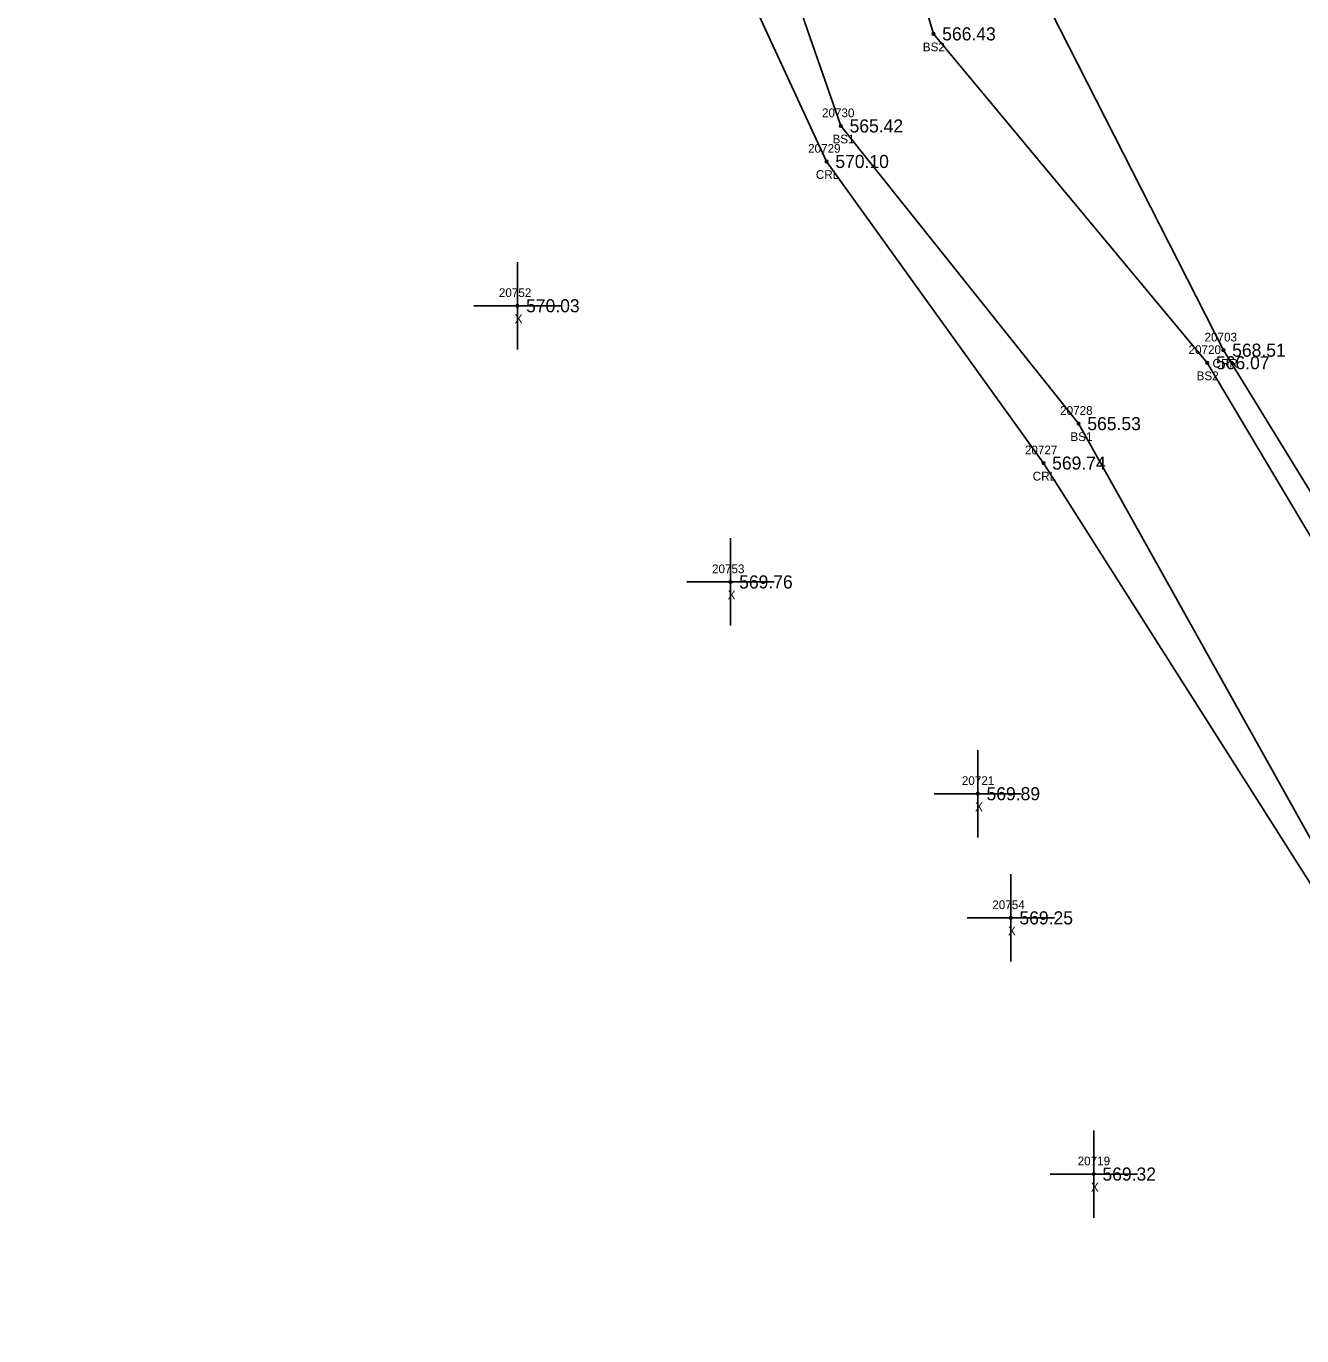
# Model space of a CAD drawing. Extents: x 1530159 to 1531652, y 877045 to 877724.
# Drawn here: x 1530609.3 to 1530755.4, y 877423 to 877573 of the extents above; entities that cross this region are included whole.
import ezdxf

# ---------------------------------------------------------------- set-up
doc = ezdxf.new("R2010")
doc.units = 0
for name, color, linetype in [('RD_DTM_BkLn2', 7, 'Continuous'), ('RD_DTM_BkLn_txCode', 7, 'Continuous'), ('RD_EX_H2O', 7, 'Continuous'), ('RD_EX_H2O_txCode', 7, 'Continuous'), ('RD_EX_Misc', 7, 'Continuous'), ('RD_EX_Misc_txCode', 7, 'Continuous'), ('RD_EX_TX_H2O_ELEV', 7, 'Continuous'), ('RD_EX_TX_Misc_ELEV', 7, 'Continuous'), ('RD_SMD_Locator', 7, 'Continuous')]:
    doc.layers.add(name, color=color, linetype=linetype)

msp = doc.modelspace()

# ---------------------------------------------------------------- linework, layer by layer
at = {"layer": 'RD_DTM_BkLn2'}
for points in [[(1530978.51, 877193.14), (1530957.83, 877217.34), (1530939.69, 877236.27), (1530919.92, 877243.6), (1530901.7, 877240.19), (1530890.91, 877253.72), (1530883.61, 877289.66), (1530871.34, 877309.06), (1530854.23, 877336.62), (1530832.44, 877361.15), (1530819.05, 877374.38), (1530808.85, 877385.69), (1530794.67, 877405.25), (1530798.76, 877416.08), (1530761.4, 877471.05), (1530729.88, 877527.47), (1530702.64, 877561.57), (1530689.57, 877599.12), (1530672.36, 877642.36), (1530634.08, 877679.71), (1530613.02, 877709.76)], [(1530924.53, 877258.32), (1530897.88, 877293.87), (1530872.66, 877332.29), (1530858.92, 877351.67), (1530825.26, 877389.74), (1530809.31, 877429.86), (1530783.89, 877460.41), (1530770.73, 877490.54), (1530744.62, 877534.44), (1530713.25, 877572.12), (1530699.86, 877617.16), (1530688.52, 877646.11), (1530631.13, 877700.3)]]:
    msp.add_lwpolyline(points, dxfattribs=at)
at = {"layer": 'RD_EX_H2O'}
for points in [[(1530806.6, 877384.6), (1530793.1, 877403.61), (1530793.09, 877415.71), (1530759.45, 877470.01), (1530725.85, 877522.95), (1530701.01, 877557.5), (1530682.02, 877598.59), (1530669.08, 877633.76), (1530634.33, 877678.03), (1530609.31, 877709.18)], [(1530922.5, 877289.86), (1530895.04, 877301.24), (1530872.88, 877333.85), (1530860.22, 877363.17), (1530828.43, 877393.28), (1530808.3, 877433.62), (1530784.24, 877462.07), (1530773.36, 877492.12), (1530746.47, 877535.88), (1530723.52, 877580.98), (1530706.2, 877619.34), (1530689.1, 877649.27), (1530633.62, 877702.51)]]:
    msp.add_lwpolyline(points, dxfattribs=at)
at = {"layer": 'RD_EX_Misc'}
for p, q in [((1530665.58, 877535.97), (1530665.58, 877545.97)), ((1530660.58, 877540.97), (1530670.58, 877540.97)), ((1530689.99, 877504.33), (1530689.99, 877514.33)), ((1530684.99, 877509.33), (1530694.99, 877509.33)), ((1530718.33, 877480.07), (1530718.33, 877490.07)), ((1530713.33, 877485.07), (1530723.33, 877485.07)), ((1530722.1, 877465.85), (1530722.1, 877475.85)), ((1530717.1, 877470.85), (1530727.1, 877470.85)), ((1530731.61, 877436.5), (1530731.61, 877446.5)), ((1530726.61, 877441.5), (1530736.61, 877441.5))]:
    msp.add_line(p, q, dxfattribs=at)
at = {"layer": 'RD_SMD_Locator'}
for centre in [(1530713.25, 877572.12), (1530702.64, 877561.57), (1530701.01, 877557.5), (1530665.58, 877540.97), (1530746.47, 877535.88), (1530744.62, 877534.44), (1530729.88, 877527.47), (1530725.85, 877522.95), (1530689.99, 877509.33), (1530718.33, 877485.07), (1530722.1, 877470.85), (1530731.61, 877441.5)]:
    msp.add_circle(centre, 0.15, dxfattribs=at)

# ---------------------------------------------------------------- texts
at = {"layer": 'RD_DTM_BkLn_txCode'}
for s, p in [('BS2', (1530712.03, 877570.12)), ('20730', (1530700.48, 877562.57)), ('BS1', (1530701.69, 877559.57)), ('20720', (1530742.47, 877535.44)), ('BS2', (1530743.4, 877532.44)), ('20728', (1530727.76, 877528.47)), ('BS1', (1530728.94, 877525.47))]:
    msp.add_text(s, height=1, dxfattribs=at).set_placement(p)
at = {"layer": 'RD_EX_H2O_txCode'}
for s, p in [('20729', (1530698.89, 877558.5)), ('CRL', (1530699.78, 877555.5)), ('20703', (1530744.31, 877536.88)), ('CRR', (1530745.22, 877533.88)), ('20727', (1530723.73, 877523.95)), ('CRL', (1530724.62, 877520.95))]:
    msp.add_text(s, height=1, dxfattribs=at).set_placement(p)
at = {"layer": 'RD_EX_Misc_txCode'}
for s, p in [('20752', (1530663.46, 877541.97)), ('X', (1530665.27, 877538.97)), ('20753', (1530687.88, 877510.33)), ('X', (1530689.68, 877507.33)), ('20721', (1530716.5, 877486.07)), ('X', (1530718.02, 877483.07)), ('20754', (1530719.99, 877471.85)), ('X', (1530721.79, 877468.85)), ('20719', (1530729.77, 877442.5)), ('X', (1530731.29, 877439.5))]:
    msp.add_text(s, height=1, dxfattribs=at).set_placement(p)
at = {"layer": 'RD_EX_TX_H2O_ELEV'}
for s, p in [('570.10', (1530702.01, 877556.75)), ('568.51', (1530747.47, 877535.13)), ('569.74', (1530726.85, 877522.2))]:
    msp.add_text(s, height=1.5, dxfattribs=at).set_placement(p)
at = {"layer": 'RD_EX_TX_Misc_ELEV'}
for s, p in [('566.43', (1530714.25, 877571.37)), ('565.42', (1530703.64, 877560.82)), ('570.03', (1530666.58, 877540.22)), ('566.07', (1530745.62, 877533.69)), ('565.53', (1530730.88, 877526.72)), ('569.76', (1530690.99, 877508.58)), ('569.89', (1530719.33, 877484.32)), ('569.25', (1530723.1, 877470.1)), ('569.32', (1530732.61, 877440.75))]:
    msp.add_text(s, height=1.5, dxfattribs=at).set_placement(p)

doc.saveas('drawing.dxf')
